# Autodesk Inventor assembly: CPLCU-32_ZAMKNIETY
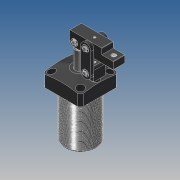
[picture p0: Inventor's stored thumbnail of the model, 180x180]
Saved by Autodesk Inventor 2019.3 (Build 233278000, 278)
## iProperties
Created: 2010-03
Part Number: CPLCU-32_ZAMKNIETY
Material: Ogólny
Document SubType Name: Assembly
Designer: CADENGINEERING4
Sending System: PRO/ENGINEER BY PARAMETRIC TECHNOLOGY CORPORATION, 2007170
Preprocessor: PRO/ENGINEER BY PARAMETRIC TECHNOLOGY CORPORATION, 2007170
Title: CPLCU-32_ASM
Author: Administrator
Revision Number: 2LAST_VERSION
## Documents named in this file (10)
- E:\SERWER_ZAPAS\MODELE brakujace\PNEUMATIC\CPLCU(STEP)\cplcu-32_asm\CPLCU-32_ZAMKNIETY.iam
- E:\SERWER_ZAPAS\MODELE brakujace\PNEUMATIC\CPLCU(STEP)\cplcu-32_asm\CPLCU-32-06.ipt
- E:\SERWER_ZAPAS\MODELE brakujace\PNEUMATIC\CPLCU(STEP)\cplcu-32_asm\CPLCU-32-07.ipt
- E:\SERWER_ZAPAS\MODELE brakujace\PNEUMATIC\CPLCU(STEP)\cplcu-32_asm\CPLCU-32-01.ipt
- E:\SERWER_ZAPAS\MODELE brakujace\PNEUMATIC\CPLCU(STEP)\cplcu-32_asm\CPLCU-32-08.ipt
- E:\SERWER_ZAPAS\MODELE brakujace\PNEUMATIC\CPLCU(STEP)\cplcu-32_asm\CPLCU-32-05.ipt
- E:\SERWER_ZAPAS\MODELE brakujace\PNEUMATIC\CPLCU(STEP)\cplcu-32_asm\CPLCU-32-02.ipt
- E:\SERWER_ZAPAS\MODELE brakujace\PNEUMATIC\CPLCU(STEP)\cplcu-32_asm\CPLCU-32-03.ipt
- E:\SERWER_ZAPAS\MODELE brakujace\PNEUMATIC\CPLCU(STEP)\cplcu-32_asm\CPLCU-32-04.ipt
- E:\SERWER_ZAPAS\MODELE brakujace\PNEUMATIC\CPLCU(STEP)\cplcu-32_asm\LHC01D-32-01.ipt
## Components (21 placed, 21 different names)
1. CPLCU-32-06_0 — Zestawiające:26
2. CPLCU-32-07_1 — Zestawiające:13, Zestawiające:16, Zestawiające:17, Zestawiające:24, Zestawiające:26
3. CPLCU-32-01_2 — Zestawiające:22, Zestawiające:23, Zestawiające:24, Zestawiające:25, Kątowe:1
4. CPLCU-32-08_3 — Zestawiające:15, Zestawiające:17, Zestawiające:19, Zestawiające:21
5. CPLCU-32-08_4 — Zestawiające:14, Zestawiające:16, Zestawiające:18, Zestawiające:20, Zestawiające:22
6. CPLCU-32-05_5 — Zestawiające:3, Zestawiające:4, Kątowe:1
7. CPLCU-32-02_6 — Zestawiające:1, Zestawiające:2, Zestawiające:3, Równoległe:3, Zestawiające:11
8. CPLCU-32-02_7 — Zestawiające:1, Zestawiające:2, Zestawiające:4, Zestawiające:5, Zestawiające:6, Równoległe:2, Zestawiające:12, Zestawiające:25
9. CPLCU-32-08_8 — Zestawiające:7, Równoległe:3
10. CPLCU-32-08_9
11. CPLCU-32-08_10 — Zestawiające:5
12. CPLCU-32-08_11 — Zestawiające:8, Równoległe:2
13. CPLCU-32-03_12 — Zestawiające:13, Zestawiające:14, Zestawiające:15, Równoległe:4
14. CPLCU-32-04_13 — Równoległe:1, Zestawiające:6, Zestawiające:7, Zestawiające:8, Zestawiające:9, Zestawiające:10, Zestawiające:23
15. CPLCU-32-04_14 — Równoległe:1
16. LHC01D-32-01_15 — Zestawiające:19, Zestawiające:21
17. LHC01D-32-01_16 — Zestawiające:18, Zestawiające:20, Równoległe:4
18. LHC01D-32-01_17 — Zestawiające:10, Zestawiające:11
19. LHC01D-32-01_18 — Zestawiające:9, Zestawiające:12
20. LHC01D-32-01_19
21. LHC01D-32-01_20
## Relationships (31: Mate 26, Flush 4, Angle 1)
- Zestawiające:1 [Mate]: CPLCU-32-02_6 ↔ CPLCU-32-02_7
- Zestawiające:2 [Mate]: CPLCU-32-02_6 ↔ CPLCU-32-02_7
- Zestawiające:3 [Mate]: CPLCU-32-05_5 ↔ CPLCU-32-02_6
- Zestawiające:4 [Mate]: CPLCU-32-05_5 ↔ CPLCU-32-02_7
- Zestawiające:5 [Mate]: CPLCU-32-02_7 ↔ CPLCU-32-08_10
- Równoległe:1 [Flush]: CPLCU-32-04_13 ↔ CPLCU-32-04_14
- Zestawiające:6 [Mate]: CPLCU-32-02_7 ↔ CPLCU-32-04_13
- Zestawiające:7 [Mate]: CPLCU-32-08_8 ↔ CPLCU-32-04_13
- Zestawiające:8 [Mate]: CPLCU-32-08_11 ↔ CPLCU-32-04_13
- Równoległe:2 [Flush]: CPLCU-32-02_7 ↔ CPLCU-32-08_11
- Równoległe:3 [Flush]: CPLCU-32-02_6 ↔ CPLCU-32-08_8
- Zestawiające:9 [Mate]: CPLCU-32-04_13 ↔ LHC01D-32-01_18
- Zestawiające:10 [Mate]: CPLCU-32-04_13 ↔ LHC01D-32-01_17
- Zestawiające:11 [Mate]: CPLCU-32-02_6 ↔ LHC01D-32-01_17
- Zestawiające:12 [Mate]: CPLCU-32-02_7 ↔ LHC01D-32-01_18
- Zestawiające:13 [Mate]: CPLCU-32-07_1 ↔ CPLCU-32-03_12
- Zestawiające:14 [Mate]: CPLCU-32-08_4 ↔ CPLCU-32-03_12
- Zestawiające:15 [Mate]: CPLCU-32-08_3 ↔ CPLCU-32-03_12
- Zestawiające:16 [Mate]: CPLCU-32-07_1 ↔ CPLCU-32-08_4
- Zestawiające:17 [Mate]: CPLCU-32-07_1 ↔ CPLCU-32-08_3
- Zestawiające:18 [Mate]: CPLCU-32-08_4 ↔ LHC01D-32-01_16
- Zestawiające:19 [Mate]: CPLCU-32-08_3 ↔ LHC01D-32-01_15
- Zestawiające:20 [Mate]: CPLCU-32-08_4 ↔ LHC01D-32-01_16
- Zestawiające:21 [Mate]: CPLCU-32-08_3 ↔ LHC01D-32-01_15
- Równoległe:4 [Flush]: CPLCU-32-03_12 ↔ LHC01D-32-01_16
- Zestawiające:22 [Mate]: CPLCU-32-01_2 ↔ CPLCU-32-08_4
- Zestawiające:23 [Mate]: CPLCU-32-01_2 ↔ CPLCU-32-04_13
- Zestawiające:24 [Mate]: CPLCU-32-07_1 ↔ CPLCU-32-01_2
- Zestawiające:25 [Mate]: CPLCU-32-01_2 ↔ CPLCU-32-02_7
- Zestawiające:26 [Mate]: CPLCU-32-06_0 ↔ CPLCU-32-07_1
- Kątowe:1 [Angle]: CPLCU-32-01_2 ↔ CPLCU-32-05_5
